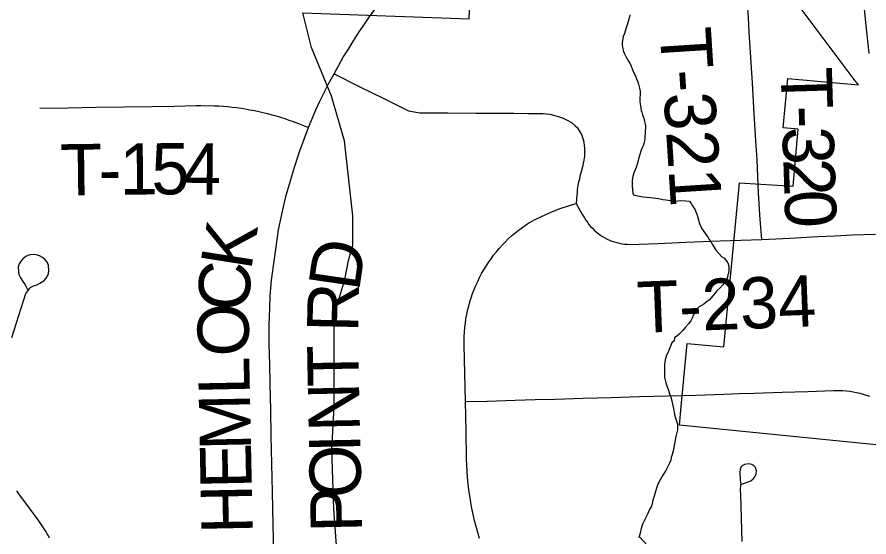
# Model space of a CAD drawing. Extents: x -11.4 to 84.1, y 11.1 to 59.
# Drawn here: x 27.281 to 28.225, y 42.977 to 43.553 of the extents above; entities that cross this region are included whole.
import ezdxf

# ---------------------------------------------------------------- set-up
doc = ezdxf.new("R2010")
doc.units = 0
for name, color, linetype in [('GM_X_Corporation', 7, 'Continuous'), ('GM_X_Minor_River', 7, 'Continuous'), ('GM_X_Township_Road', 7, 'Continuous'), ('GM_X_Township_Road_Text', 7, 'Continuous')]:
    doc.layers.add(name, color=color, linetype=linetype)

msp = doc.modelspace()

# ---------------------------------------------------------------- linework, layer by layer
at = {"layer": 'GM_X_Corporation'}
for points in [[(28.39493, 43.06284), (28.01471, 43.10114), (28.01642, 43.12177), (28.02321, 43.19167), (28.06371, 43.18776), (28.08095, 43.36972), (28.14049, 43.36615), (28.14607, 43.42915), (28.12965, 43.43068), (28.13476, 43.48525), (28.21277, 43.47818), (28.2091, 43.48293), (28.10396, 43.6235), (28.26522, 43.76952)], [(27.63544, 42.95751), (27.63165, 43.0084), (27.62938, 43.07411), (27.63204, 43.1212), (27.63225, 43.22236), (27.63841, 43.24417), (27.64404, 43.26266), (27.64805, 43.28356), (27.65287, 43.30045), (27.65294, 43.33325), (27.64345, 43.4163), (27.62902, 43.46569), (27.607, 43.51963), (27.59725, 43.55802), (27.78185, 43.55134), (27.78398, 43.60307)]]:
    msp.add_lwpolyline(points, dxfattribs=at)
at = {"layer": 'GM_X_Minor_River'}
for points in [[(27.95976, 43.55588), (27.9587, 43.55129), (27.95689, 43.54594), (27.95508, 43.54059), (27.95365, 43.53524), (27.95219, 43.53179), (27.95117, 43.52493), (27.95121, 43.52265), (27.95162, 43.52038), (27.95204, 43.5181), (27.95247, 43.51545), (27.95365, 43.51281), (27.95522, 43.50979), (27.95678, 43.50715), (27.95835, 43.50452), (27.95992, 43.5015), (27.9611, 43.49886), (27.96229, 43.49622), (27.96347, 43.4932), (27.96466, 43.49055), (27.96584, 43.48791), (27.96703, 43.48489), (27.96822, 43.48225), (27.96941, 43.47922), (27.97024, 43.47468), (27.97106, 43.47127), (27.97111, 43.46822), (27.97081, 43.46328), (27.97088, 43.45948), (27.97133, 43.45492), (27.97175, 43.45265), (27.97218, 43.44999), (27.97297, 43.4481), (27.97378, 43.44507), (27.97498, 43.44129), (27.9758, 43.4375), (27.97661, 43.43485), (27.97702, 43.43296), (27.97707, 43.42992), (27.97673, 43.42763), (27.97678, 43.42497), (27.97645, 43.42154), (27.97612, 43.41849), (27.97578, 43.41621), (27.97508, 43.41316), (27.97435, 43.41086), (27.97289, 43.40779), (27.97216, 43.40588), (27.96928, 43.39633), (27.96894, 43.39404), (27.96786, 43.39022), (27.96678, 43.38678), (27.96569, 43.3841), (27.96459, 43.38142), (27.96387, 43.37913), (27.96315, 43.37684), (27.96242, 43.37492), (27.96209, 43.37226), (27.96213, 43.36959), (27.96219, 43.36617), (27.96263, 43.36238), (27.96308, 43.3582), (27.96388, 43.35631), (27.96845, 43.35525)], [(27.96845, 43.35525), (27.97455, 43.35421), (27.98253, 43.35358), (27.99129, 43.3522), (27.99625, 43.35114), (27.99967, 43.35082), (28.00196, 43.35048), (28.00424, 43.35013), (28.00652, 43.34979), (28.00995, 43.34947), (28.01564, 43.34994), (28.02172, 43.34966), (28.0259, 43.34935), (28.02747, 43.34671), (28.02903, 43.34408), (28.03059, 43.34182), (28.03215, 43.33957), (28.03294, 43.33768), (28.03374, 43.33503), (28.03494, 43.33125), (28.03696, 43.32444), (28.03894, 43.31952), (28.04595, 43.30937), (28.04751, 43.30674), (28.04945, 43.30449), (28.05101, 43.30185), (28.05258, 43.29884), (28.05492, 43.29507), (28.0584, 43.29133), (28.06112, 43.28795), (28.0638, 43.28647), (28.06613, 43.28385), (28.06808, 43.28084), (28.06887, 43.27895), (28.06929, 43.2763), (28.06935, 43.27288), (28.06903, 43.26945), (28.0683, 43.26753), (28.06796, 43.26525), (28.06724, 43.26295), (28.06502, 43.2595), (28.06279, 43.25642), (28.05943, 43.25294), (28.05606, 43.24984), (28.05383, 43.24714), (28.05122, 43.24406), (28.04788, 43.23982), (28.04374, 43.23709), (28.0415, 43.23515), (28.03886, 43.23359), (28.03661, 43.23203), (28.03436, 43.23009), (28.0325, 43.22778), (28.03141, 43.2251), (28.02994, 43.22242), (28.02884, 43.21974), (28.02737, 43.21667), (28.02477, 43.2132), (28.02141, 43.20973), (28.01844, 43.20588), (28.01433, 43.20201), (28.01171, 43.19968), (28.00908, 43.19774), (28.00875, 43.19469), (28.00613, 43.19237), (28.00322, 43.18509), (28.00176, 43.18127), (28.00029, 43.17858), (27.99957, 43.17591), (27.99885, 43.17361), (27.99852, 43.17095), (27.99818, 43.16828), (27.99787, 43.16447), (27.99793, 43.16067), (27.99799, 43.15725), (27.99805, 43.15383), (27.99886, 43.1508), (27.99967, 43.14777), (28.00088, 43.14361), (28.00246, 43.13983), (28.00367, 43.13567), (28.00525, 43.13189), (28.00607, 43.1281), (28.0069, 43.12431), (28.00812, 43.11939), (28.00899, 43.11294), (28.0106, 43.10765), (28.01179, 43.10424), (28.01259, 43.10235), (28.01263, 43.09969), (28.01231, 43.09589), (28.01161, 43.09283), (28.01054, 43.08863), (28.00985, 43.08444), (28.00916, 43.08024), (28.00846, 43.07643), (28.00777, 43.07262), (28.0067, 43.06842), (28.00561, 43.06536), (28.0049, 43.06231), (28.00344, 43.05886)], [(28.00344, 43.05886), (28.00197, 43.05579), (27.9994, 43.05081), (27.99607, 43.04543), (27.99312, 43.04044), (27.99091, 43.03622), (27.98945, 43.03239), (27.98802, 43.02743), (27.98658, 43.02246), (27.98549, 43.0194), (27.98479, 43.01597), (27.98373, 43.01138), (27.98152, 43.00755), (27.97969, 43.00295), (27.97381, 42.99145), (27.97237, 42.98648), (27.97094, 42.98114), (27.96951, 42.97617)], [(27.96995, 42.97769), (27.9981, 42.94736)]]:
    msp.add_lwpolyline(points, dxfattribs=at)
at = {"layer": 'GM_X_Township_Road'}
for points in [[(28.2246, 43.51302), (28.22153, 43.54394), (28.21901, 43.56946), (28.21648, 43.59498), (28.21606, 43.60022), (28.21573, 43.6055), (28.21554, 43.61077), (28.21584, 43.62658), (28.21622, 43.63185), (28.21669, 43.63709), (28.21736, 43.64233), (28.21812, 43.64755), (28.21902, 43.65275), (28.22002, 43.65791), (28.2212, 43.66307), (28.22248, 43.66817), (28.22396, 43.67326), (28.22547, 43.67829)], [(27.56524, 42.95941), (27.56453, 42.99047), (27.56412, 43.00871), (27.56371, 43.02696), (27.56309, 43.05802), (27.56247, 43.08908), (27.56188, 43.11805), (27.5613, 43.14702), (27.5608, 43.16882), (27.5603, 43.19062), (27.5602, 43.21159), (27.56069, 43.2308), (27.56117, 43.24426), (27.56263, 43.26182), (27.56596, 43.28555), (27.56825, 43.30148), (27.57054, 43.31742), (27.57512, 43.33985), (27.57853, 43.35457), (27.58336, 43.37082), (27.58819, 43.38705), (27.59424, 43.40529), (27.60358, 43.43102), (27.60811, 43.44177), (27.61184, 43.45077), (27.61616, 43.46021), (27.62589, 43.47951), (27.63215, 43.49035), (27.64206, 43.50892), (27.64784, 43.51792), (27.65339, 43.52692), (27.65908, 43.53582), (27.66491, 43.54462), (27.67093, 43.55333), (27.6771, 43.56192)], [(28.10584, 43.30694), (28.10398, 43.32898), (28.10232, 43.35834), (28.1015, 43.37668), (28.10067, 43.39501), (28.09911, 43.41608), (28.09813, 43.43441), (28.09715, 43.45275), (28.0954, 43.48064), (28.09359, 43.50859), (28.09179, 43.53654), (28.09097, 43.55263), (28.09015, 43.56872)], [(27.63215, 43.49035), (27.66001, 43.47659), (27.68727, 43.46313), (27.71453, 43.44967), (27.72714, 43.44746), (27.75821, 43.44727), (27.78928, 43.44707), (27.81016, 43.44694), (27.83105, 43.44681), (27.84736, 43.4467), (27.86369, 43.44659), (27.87085, 43.4459), (27.87917, 43.44356), (27.88567, 43.44135), (27.89104, 43.43893), (27.89492, 43.43651), (27.89871, 43.43328), (27.90128, 43.43088), (27.90317, 43.42799), (27.90595, 43.4234), (27.9083, 43.41677), (27.90913, 43.41147), (27.90948, 43.40755), (27.90955, 43.40374), (27.90925, 43.39898), (27.9083, 43.3931), (27.90706, 43.38743), (27.90538, 43.38048), (27.90442, 43.37697), (27.90377, 43.37382), (27.90289, 43.37038), (27.90209, 43.3668), (27.90143, 43.36212), (27.90114, 43.3589), (27.90075, 43.35188), (27.90036, 43.34668), (27.90413, 43.33937), (27.9073, 43.33437), (27.90953, 43.33084), (27.91099, 43.32837), (27.91265, 43.32597), (27.91435, 43.32365), (27.91625, 43.32142), (27.91819, 43.31929), (27.92028, 43.31726), (27.92241, 43.31533), (27.92468, 43.31351), (27.927, 43.31181), (27.92947, 43.31022), (27.93193, 43.30875), (27.93453, 43.30741), (27.93714, 43.3062), (27.93984, 43.30512), (27.94258, 43.30418), (27.94533, 43.30337), (27.94817, 43.3027), (27.95101, 43.30217), (27.9539, 43.30178), (27.95679, 43.30154), (27.95969, 43.30143), (27.99073, 43.3026), (28.02178, 43.30378), (28.0407, 43.3045), (28.05961, 43.30521), (28.08272, 43.30608), (28.10584, 43.30694), (28.13687, 43.30847), (28.1679, 43.31), (28.18684, 43.31094), (28.20578, 43.31187), (28.23176, 43.31271)], [(27.30617, 43.45247), (27.33723, 43.45296), (27.36829, 43.45346), (27.39936, 43.45396), (27.43042, 43.45445), (27.45491, 43.45485), (27.47939, 43.45524), (27.48436, 43.45534), (27.49928, 43.45512), (27.50426, 43.45488), (27.50923, 43.45454), (27.51421, 43.45412), (27.51914, 43.45361), (27.52411, 43.45303), (27.52904, 43.45234), (27.53396, 43.45158), (27.53884, 43.45073), (27.54373, 43.44979), (27.5486, 43.44877), (27.55348, 43.44766), (27.55832, 43.44648), (27.5631, 43.4452), (27.56788, 43.44384), (27.57267, 43.44239), (27.5774, 43.44086), (27.58209, 43.43926), (27.58679, 43.43756), (27.59252, 43.43537), (27.60358, 43.43102)], [(27.79311, 42.97548), (27.79117, 42.98208), (27.78932, 42.98874), (27.78767, 42.99544), (27.78615, 43.00215), (27.78479, 43.0089), (27.78356, 43.01568), (27.78247, 43.02249), (27.78147, 43.02931), (27.78067, 43.03616), (27.78001, 43.04302), (27.7795, 43.04989), (27.77912, 43.05677), (27.77888, 43.06365), (27.77832, 43.09471), (27.77803, 43.11102), (27.77773, 43.12733), (27.77694, 43.15838), (27.77654, 43.17405), (27.77614, 43.18972), (27.77624, 43.19944), (27.77648, 43.2043), (27.77691, 43.20914), (27.77743, 43.21398), (27.77815, 43.21879), (27.779, 43.22357), (27.78, 43.22833), (27.78119, 43.23304), (27.78247, 43.23773), (27.78389, 43.24237), (27.7855, 43.24697), (27.78721, 43.25152), (27.78906, 43.25601), (27.7911, 43.26044), (27.79324, 43.26481), (27.79551, 43.26911), (27.79788, 43.27333), (27.80044, 43.27747), (27.8031, 43.28154), (27.80589, 43.28553), (27.80878, 43.28942), (27.81182, 43.29323), (27.81495, 43.29693), (27.81822, 43.30054), (27.82158, 43.30406), (27.82504, 43.30746), (27.82865, 43.31075), (27.8323, 43.31393), (27.83609, 43.31699), (27.83993, 43.31993), (27.84391, 43.32276), (27.84794, 43.32546), (27.8564, 43.3299), (27.86109, 43.33211), (27.87136, 43.33679), (27.88151, 43.34076), (27.89264, 43.34468), (27.90036, 43.34668)], [(27.29527, 43.25312), (27.29596, 43.25389), (27.29909, 43.25539), (27.30291, 43.25667), (27.30604, 43.25829), (27.31044, 43.26095), (27.31311, 43.26397), (27.31496, 43.26686), (27.31566, 43.26906), (27.31624, 43.27242), (27.31566, 43.27821), (27.3145, 43.28123), (27.31195, 43.28447), (27.30917, 43.28691), (27.3057, 43.28876), (27.30245, 43.2898), (27.29909, 43.29038), (27.29526, 43.2898), (27.29295, 43.28899), (27.29064, 43.28783), (27.2889, 43.28656), (27.28739, 43.28552), (27.2853, 43.28332), (27.28333, 43.27984), (27.28206, 43.27613), (27.28287, 43.26814), (27.28438, 43.26501), (27.28646, 43.26153), (27.28994, 43.25678), (27.29249, 43.25157)], [(27.2752, 43.19836), (27.28292, 43.22265), (27.29064, 43.24693), (27.29388, 43.25157), (27.29527, 43.25312)], [(27.77773, 43.12733), (27.80143, 43.12777), (27.83248, 43.1287), (27.85475, 43.12937), (27.87702, 43.13003), (27.90807, 43.1309), (27.93913, 43.13176), (27.97018, 43.13263), (28.00124, 43.1335), (28.01701, 43.13394), (28.03278, 43.13438), (28.06383, 43.13541), (28.0806, 43.13597), (28.09735, 43.13653), (28.1284, 43.13753), (28.15687, 43.13844), (28.18533, 43.13936), (28.19575, 43.13951), (28.19954, 43.13918), (28.20328, 43.1387), (28.20698, 43.13811), (28.21067, 43.13738), (28.21436, 43.13653), (28.21801, 43.13554), (28.22162, 43.13444), (28.22517, 43.13321)], [(28.08406, 42.9719), (28.08324, 42.99777), (28.08243, 43.02365), (28.08234, 43.0289), (28.08247, 43.03475), (28.08257, 43.03529), (28.08295, 43.0356), (28.08347, 43.03577), (28.08543, 43.03641), (28.08952, 43.0377), (28.09353, 43.03942), (28.09628, 43.04162), (28.09812, 43.04357), (28.09966, 43.04687), (28.09981, 43.0504), (28.09886, 43.05392), (28.09702, 43.05612), (28.09474, 43.05729), (28.09159, 43.05803), (28.08653, 43.05759), (28.08412, 43.05609), (28.08252, 43.0543), (28.08185, 43.05222), (28.0816, 43.04858), (28.08191, 43.0399), (28.08268, 43.03571)], [(27.31686, 42.97583), (27.31563, 42.97816), (27.31435, 42.98047), (27.31302, 42.98277), (27.31165, 42.98503), (27.31023, 42.98728), (27.30881, 42.9895), (27.30734, 42.99169), (27.30583, 42.99386), (27.30426, 42.99599), (27.29472, 43.0089), (27.28518, 43.02181), (27.28362, 43.02394), (27.2821, 43.02611), (27.28064, 43.02832)]]:
    msp.add_lwpolyline(points, dxfattribs=at)

# ---------------------------------------------------------------- texts
at = {"layer": 'GM_X_Township_Road_Text'}
for s, height, rotation, p in [('T-321', 0.056818, 273.64662, (27.99258, 43.54026)), ('T', 0.05682, 271.6673, (28.12663, 43.4972)), ('-', 0.05682, 271.68111, (28.12787, 43.45471)), ('3', 0.05682, 271.71175, (28.12855, 43.43135)), ('T', 0.05682, 0.75001, (27.329, 43.35562)), ('1', 0.05682, 0.5516, (27.39477, 43.35646)), ('5', 0.05682, 0.19255, (27.42968, 43.3568)), ('4', 0.05682, 359.39631, (27.46447, 43.35692)), ('2', 0.05682, 271.84245, (28.1296, 43.39622)), ('-', 0.05682, 0.7026, (27.37148, 43.35618)), ('0', 0.05682, 272.20103, (28.13074, 43.36086)), ('K', 0.05682, 81.02036, (27.54006, 43.27159)), ('D', 0.05682, 81.70915, (27.65959, 43.24836)), ('C', 0.05682, 86.49304, (27.53736, 43.22643)), ('T-234', 0.056818, 2.19044, (27.96867, 43.20324)), ('R', 0.05682, 88.70016, (27.65868, 43.20354)), ('O', 0.05682, 90.71767, (27.53801, 43.17755)), ('T', 0.05682, 91.05862, (27.65974, 43.14416)), ('L', 0.05682, 91.16574, (27.53888, 43.13517)), ('N', 0.05682, 91.1658, (27.66075, 43.0942)), ('M', 0.05682, 91.16933, (27.54014, 43.07352)), ('I', 0.05682, 91.19089, (27.66124, 43.07088)), ('E', 0.05682, 91.16774, (27.541, 43.03103)), ('O', 0.05682, 91.18037, (27.66227, 43.02088)), ('H', 0.05682, 91.16945, (27.54202, 42.98104)), ('P', 0.05682, 91.18321, (27.66306, 42.98256))]:
    msp.add_text(s, height=height, rotation=rotation, dxfattribs=at).set_placement(p)

doc.saveas('drawing.dxf')
